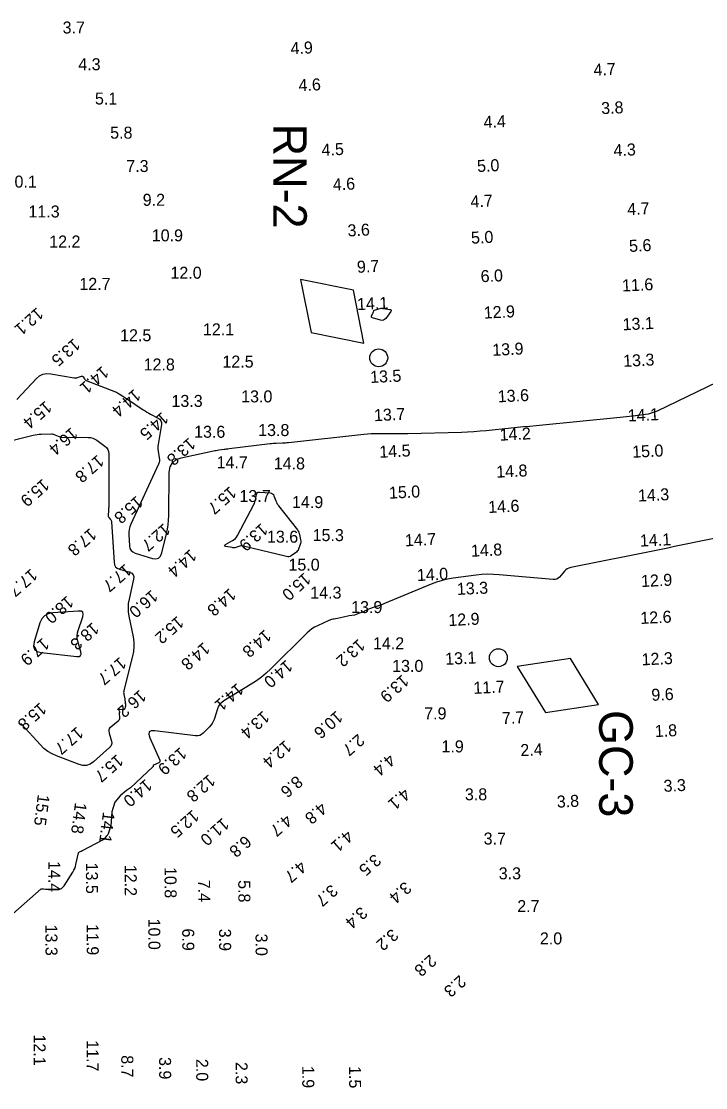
# Model space of a CAD drawing. Extents: x 824616 to 827440, y 158441 to 163197.
# Drawn here: x 824849.5 to 825134.8, y 161170.8 to 161615.4 of the extents above; entities that cross this region are included whole.
import ezdxf

# ---------------------------------------------------------------- set-up
doc = ezdxf.new("R2010")
doc.units = 0
for name, color, linetype in [('V-CHAN-CONT-EL14', 7, 'Continuous'), ('V-CHAN-CONT-EL16', 7, 'Continuous'), ('V-CHAN-CONT-EL18', 7, 'Continuous'), ('V-CHAN-NAID', 7, 'Continuous'), ('V-TOPO-SOUN', 7, 'Continuous')]:
    doc.layers.add(name, color=color, linetype=linetype)

msp = doc.modelspace()

# ---------------------------------------------------------------- linework, layer by layer
at = {"layer": 'V-CHAN-CONT-EL14'}
for points in [[(824996.49, 161494.89), (824996.58, 161494.95), (824996.69, 161495), (824999.41, 161495.78), (824999.49, 161495.8), (824999.58, 161495.8), (824999.66, 161495.8), (824999.74, 161495.78), (825000.08, 161495.67), (825000.17, 161495.65), (825000.25, 161495.63), (825000.34, 161495.61), (825000.43, 161495.6), (825003.11, 161495.3), (825003.49, 161495.2), (825003.68, 161495.02), (825003.68, 161494.76), (825003.49, 161494.42), (825001.37, 161491.53), (825000.93, 161491.07), (825000.43, 161490.8), (824999.87, 161490.71), (824999.24, 161490.8), (824995.8, 161491.79), (824995.58, 161491.89), (824995.46, 161492.03), (824995.43, 161492.21), (824995.49, 161492.44), (824996.04, 161493.72), (824996.09, 161493.84), (824996.14, 161493.95), (824996.18, 161494.07), (824996.22, 161494.2), (824996.37, 161494.69), (824996.42, 161494.8)], [(824946.81, 161414.9), (824946.96, 161415.42), (824947.07, 161415.96), (824947.45, 161418.13), (824947.6, 161418.6), (824947.86, 161418.92), (824948.24, 161419.1), (824948.74, 161419.13), (824953.24, 161418.78), (824953.77, 161418.68), (824954.2, 161418.45), (824954.54, 161418.09), (824954.78, 161417.61), (824955.57, 161415.44), (824955.79, 161414.91), (824956.04, 161414.4), (824956.34, 161413.92), (824956.67, 161413.45), (824964.57, 161403.34), (824964.88, 161402.9), (824965.13, 161402.43), (824965.33, 161401.93), (824965.47, 161401.41), (824965.92, 161399.2), (824965.99, 161398.7), (824965.99, 161398.2), (824965.91, 161397.71), (824965.76, 161397.23), (824965.03, 161395.31), (824964.81, 161394.85), (824964.53, 161394.44), (824964.19, 161394.09), (824963.79, 161393.78), (824961.95, 161392.57), (824961.49, 161392.33), (824961.01, 161392.2), (824960.51, 161392.17), (824960, 161392.24), (824942.13, 161396.62), (824941.72, 161396.69), (824941.32, 161396.71), (824940.92, 161396.67), (824940.52, 161396.57), (824938.92, 161396.06), (824938.52, 161395.96), (824938.12, 161395.91), (824937.71, 161395.92), (824937.3, 161395.97), (824934.77, 161396.45), (824934.35, 161396.57), (824934.18, 161396.75), (824934.28, 161396.96), (824934.64, 161397.23), (824937.57, 161398.92), (824938.18, 161399.33), (824938.72, 161399.82), (824939.18, 161400.38), (824939.57, 161401.01), (824946.37, 161413.9), (824946.61, 161414.39)]]:
    msp.add_lwpolyline(points, close=True, dxfattribs=at)
for points in [[(824847.55, 161457.69), (824855.79, 161466.49), (824857.08, 161467.58), (824858.49, 161468.28), (824860.04, 161468.57), (824861.72, 161468.47), (824871.48, 161466.8), (824871.84, 161466.76), (824872.21, 161466.77), (824872.57, 161466.81), (824872.92, 161466.91), (824874.6, 161467.44), (824874.81, 161467.48), (824875, 161467.45), (824875.17, 161467.34), (824875.3, 161467.17), (824875.79, 161466.32), (824875.93, 161466.13), (824876.09, 161465.96), (824876.27, 161465.83), (824876.49, 161465.72), (824888.72, 161460.89), (824889.13, 161460.72), (824889.54, 161460.52), (824889.93, 161460.3), (824890.31, 161460.07), (824891.82, 161459.08), (824892.19, 161458.83), (824892.57, 161458.59), (824892.94, 161458.34), (824893.32, 161458.09), (824900.31, 161453.44), (824901.06, 161452.96), (824901.83, 161452.49), (824902.6, 161452.05), (824903.39, 161451.62), (824906.57, 161449.96), (824907.24, 161449.49), (824907.68, 161448.9), (824907.89, 161448.19), (824907.86, 161447.37), (824906.45, 161438.94), (824906.37, 161438.25), (824906.35, 161437.57), (824906.38, 161436.88), (824906.48, 161436.2), (824907, 161433.46), (824907.07, 161432.78), (824907.05, 161432.12), (824906.91, 161431.46), (824906.67, 161430.82), (824895.09, 161405.73), (824894.67, 161404.67), (824894.4, 161403.59), (824894.26, 161402.47), (824894.26, 161401.33), (824894.55, 161396.73), (824894.75, 161395.67), (824895.21, 161394.83), (824895.93, 161394.18), (824896.9, 161393.74), (824904.14, 161391.51), (824905.57, 161391.29), (824906.7, 161391.59), (824907.53, 161392.41), (824908.06, 161393.75), (824909.95, 161401.75), (824910.35, 161403.63), (824910.63, 161405.51), (824910.82, 161407.42), (824910.9, 161409.33), (824911.17, 161427.4), (824911.5, 161429.64), (824912.44, 161431.39), (824913.97, 161432.65), (824916.11, 161433.41), (824929.62, 161436.3), (824930.16, 161436.41), (824930.7, 161436.51), (824931.24, 161436.6), (824931.79, 161436.69), (824933.98, 161437), (824934.52, 161437.08), (824935.07, 161437.16), (824935.62, 161437.23), (824936.16, 161437.29), (824953.16, 161439.36), (824953.8, 161439.43), (824954.44, 161439.48), (824955.08, 161439.53), (824955.72, 161439.56), (824958.3, 161439.66), (824958.94, 161439.69), (824959.58, 161439.73), (824960.22, 161439.78), (824960.86, 161439.84), (824992.2, 161443.24), (824993.73, 161443.39), (824995.25, 161443.49), (824996.78, 161443.54), (824998.31, 161443.55), (825004.43, 161443.51), (825005.96, 161443.5), (825007.49, 161443.51), (825009.03, 161443.53), (825010.56, 161443.57), (825032.91, 161444.18), (825035.51, 161444.28), (825038.11, 161444.42), (825040.71, 161444.61), (825043.3, 161444.85), (825053.66, 161445.89), (825056.26, 161446.15), (825058.85, 161446.41), (825061.44, 161446.67), (825064.03, 161446.92), (825099.04, 161450.39), (825100.37, 161450.53), (825101.69, 161450.67), (825103.01, 161450.81), (825104.34, 161450.97), (825109.63, 161451.59), (825110.93, 161451.8), (825112.21, 161452.11), (825113.46, 161452.53), (825114.67, 161453.06), (825139.69, 161465.12)], [(825161.56, 161404.52), (825124.51, 161397.04), (825123.82, 161396.9), (825123.13, 161396.75), (825122.44, 161396.6), (825121.75, 161396.44), (825118.99, 161395.81), (825118.3, 161395.65), (825117.61, 161395.5), (825116.92, 161395.35), (825116.23, 161395.21), (825078.51, 161387.69), (825077.76, 161387.48), (825077.08, 161387.16), (825076.46, 161386.72), (825075.91, 161386.17), (825073.84, 161383.73), (825073.29, 161383.21), (825072.67, 161382.85), (825071.98, 161382.67), (825071.22, 161382.66), (825048.68, 161384.69), (825046.28, 161384.84), (825043.89, 161384.86), (825041.49, 161384.74), (825039.1, 161384.49), (825029.55, 161383.22), (825027.18, 161382.82), (825024.85, 161382.28), (825022.56, 161381.58), (825020.32, 161380.73), (825000.86, 161372.65), (825000.36, 161372.45), (824999.86, 161372.25), (824999.35, 161372.06), (824998.84, 161371.88), (824996.54, 161371.09), (824996.16, 161370.96), (824995.79, 161370.83), (824995.41, 161370.69), (824995.04, 161370.55), (824993.54, 161369.99), (824993.21, 161369.82), (824992.67, 161369.58), (824992.2, 161369.28), (824991.4, 161368.91), (824990.38, 161368.61), (824988.32, 161367.82), (824986.08, 161367.52), (824983.78, 161366.97), (824981.29, 161366.43), (824980.5, 161366.29), (824979.9, 161366.15), (824979.42, 161366.13), (824978.78, 161365.95), (824977.65, 161365.6), (824972.88, 161363.37), (824971.72, 161362.76), (824970.62, 161362.07), (824969.59, 161361.28), (824968.62, 161360.4), (824953.45, 161345.41), (824951.55, 161343.64), (824949.56, 161341.99), (824947.48, 161340.46), (824945.3, 161339.04), (824933.85, 161332.07), (824932.99, 161331.43), (824932.27, 161330.68), (824931.7, 161329.82), (824931.29, 161328.83), (824929.82, 161324.32), (824929.49, 161323.46), (824929.06, 161322.66), (824928.54, 161321.92), (824927.93, 161321.23), (824925.28, 161318.6), (824924.59, 161318.03), (824923.83, 161317.67), (824923, 161317.49), (824922.11, 161317.51), (824905.18, 161319.66), (824903.67, 161319.65), (824902.8, 161319.17), (824902.59, 161318.2), (824903.01, 161316.75), (824907.18, 161307.4), (824907.28, 161307.04), (824907.24, 161306.73), (824907.07, 161306.48), (824906.75, 161306.28), (824904.55, 161305.29), (824904.49, 161305.26), (824904.46, 161305.22), (824904.43, 161305.17), (824904.43, 161305.1), (824904.44, 161304.84), (824904.43, 161304.77), (824904.41, 161304.71), (824904.38, 161304.66), (824904.34, 161304.61), (824894.92, 161295.9), (824893.28, 161294.72), (824890.66, 161292.5), (824888.39, 161289.81), (824887.15, 161285.77), (824886.77, 161279.88)], [(824830.5, 161229.86), (824857.8, 161253.75), (824858.65, 161253.69), (824859.51, 161253.64), (824860.37, 161253.6), (824861.22, 161253.59), (824864.66, 161253.58), (824865.46, 161253.67), (824866.17, 161253.94), (824866.78, 161254.39), (824867.29, 161255.02), (824870.93, 161260.75), (824871.37, 161261.5), (824871.73, 161262.28), (824872.03, 161263.09), (824872.25, 161263.92), (824873.33, 161268.68), (824873.39, 161268.84), (824873.47, 161268.97), (824873.59, 161269.08), (824873.73, 161269.16), (824874.37, 161269.43), (824874.53, 161269.5), (824874.68, 161269.57), (824874.84, 161269.65), (824874.99, 161269.73), (824883.49, 161274.17), (824883.75, 161274.32), (824883.98, 161274.49), (824884.2, 161274.69), (824884.4, 161274.91), (824885.17, 161275.82), (824885.35, 161276.06), (824885.51, 161276.31), (824885.65, 161276.57), (824885.76, 161276.84), (824886.68, 161279.32), (824886.79, 161279.71), (824886.77, 161279.88)]]:
    msp.add_lwpolyline(points, dxfattribs=at)
at = {"layer": 'V-CHAN-CONT-EL16'}
msp.add_lwpolyline([(824838.91, 161438.98), (824854.39, 161442.87), (824855.21, 161443.05), (824856.04, 161443.19), (824856.88, 161443.27), (824857.72, 161443.31), (824862.02, 161443.37), (824862.4, 161443.36), (824862.77, 161443.3), (824863.14, 161443.2), (824863.49, 161443.05), (824864.89, 161442.39), (824865.25, 161442.25), (824865.61, 161442.14), (824865.99, 161442.08), (824866.37, 161442.06), (824877.33, 161441.94), (824878.32, 161441.85), (824879.27, 161441.62), (824880.16, 161441.24), (824881.01, 161440.71), (824884.29, 161438.31), (824885.01, 161437.66), (824885.52, 161436.9), (824885.82, 161436.04), (824885.92, 161435.07), (824885.89, 161412.78), (824885.88, 161412.4), (824885.87, 161412.02), (824885.84, 161411.64), (824885.81, 161411.25), (824885.63, 161409.5), (824885.63, 161409.24), (824885.68, 161408.99), (824885.78, 161408.76), (824885.93, 161408.55), (824886.65, 161407.73), (824886.81, 161407.52), (824886.93, 161407.29), (824887.01, 161407.04), (824887.04, 161406.78), (824888.11, 161389.87), (824888.3, 161388.86), (824888.74, 161388.04), (824889.43, 161387.42), (824890.37, 161387), (824894.61, 161385.7), (824895.51, 161385.27), (824896.08, 161384.66), (824896.33, 161383.86), (824896.25, 161382.88), (824894.37, 161374.47), (824894.07, 161372.71), (824893.96, 161370.95), (824894.04, 161369.18), (824894.3, 161367.41), (824896.07, 161358.78), (824896.37, 161356.75), (824896.43, 161354.73), (824896.27, 161352.72), (824895.88, 161350.71), (824892.24, 161336.4), (824892.16, 161335.99), (824892.13, 161335.58), (824892.14, 161335.17), (824892.2, 161334.75), (824892.57, 161332.88), (824892.62, 161332.57), (824892.67, 161332.26), (824892.71, 161331.94), (824892.73, 161331.63), (824892.85, 161329.98), (824892.86, 161329.86), (824892.85, 161329.74), (824892.83, 161329.62), (824892.79, 161329.5), (824892.62, 161328.97), (824892.59, 161328.89), (824892.55, 161328.81), (824892.5, 161328.75), (824892.45, 161328.68), (824892.21, 161328.45), (824892.14, 161328.39), (824892.08, 161328.36), (824892, 161328.34), (824891.92, 161328.35), (824890.38, 161328.54), (824890.24, 161328.54), (824890.16, 161328.5), (824890.14, 161328.41), (824890.18, 161328.28), (824890.56, 161327.43), (824890.57, 161327.39), (824890.57, 161327.37), (824890.55, 161327.34), (824890.52, 161327.33), (824890.38, 161327.26), (824890.35, 161327.24), (824890.33, 161327.22), (824890.32, 161327.19), (824890.31, 161327.15), (824890.38, 161324.94), (824890.35, 161324.58), (824890.25, 161324.25), (824890.07, 161323.95), (824889.81, 161323.69), (824886.79, 161321.18), (824886.29, 161320.65), (824886, 161320.06), (824885.92, 161319.4), (824886.04, 161318.69), (824887.06, 161315.36), (824887.2, 161314.58), (824887.11, 161313.87), (824886.81, 161313.22), (824886.29, 161312.64), (824879.53, 161306.65), (824878.15, 161305.7), (824876.69, 161305.2), (824875.14, 161305.15), (824873.52, 161305.56), (824864.19, 161309.12), (824862.29, 161309.98), (824860.53, 161311.03), (824858.91, 161312.28), (824857.42, 161313.74), (824849.57, 161322.34), (824849.26, 161322.71)], dxfattribs=at)
at = {"layer": 'V-CHAN-CONT-EL18'}
msp.add_lwpolyline([(824854.97, 161353.59), (824856.02, 161352.7), (824857.74, 161352.25), (824872.57, 161350.58), (824873.54, 161350.61), (824874.15, 161350.95), (824874.39, 161351.6), (824874.25, 161352.56), (824872.99, 161357.05), (824872.76, 161358.17), (824872.71, 161359.28), (824872.83, 161360.39), (824873.12, 161361.49), (824875.07, 161367.11), (824875.29, 161368.24), (824875.06, 161369.02), (824874.37, 161369.45), (824873.22, 161369.53), (824862.56, 161368.79), (824860.68, 161368.42), (824859.17, 161367.59), (824858.02, 161366.31), (824857.24, 161364.56), (824854.84, 161356.67), (824854.57, 161354.91)], close=True, dxfattribs=at)
at = {"layer": 'V-CHAN-NAID'}
for points in [[(824992.29, 161481.27), (824987.88, 161503.31), (824965.84, 161507.72), (824970.25, 161485.68)], [(825056.24, 161346.39), (825067.92, 161327.19), (825090.14, 161330.59), (825078.46, 161349.79)]]:
    msp.add_lwpolyline(points, close=True, dxfattribs=at)
for centre in [(824998.46, 161475.1), (825048.33, 161350.08)]:
    msp.add_circle(centre, 3.74, dxfattribs=at)

# ---------------------------------------------------------------- texts
for s, p in [('RN-2', (824954.46, 161572.71)), ('GC-3', (825090.36, 161328.26))]:
    msp.add_text(s, height=14, rotation=270, dxfattribs=at).set_placement(p)
at = {"layer": 'V-TOPO-SOUN'}
for s, p in [('3.7', (824866.68, 161610.31)), ('4.3', (824873.23, 161594.99)), ('5.1', (824880.17, 161580.71)), ('5.8', (824886.51, 161566.47)), ('7.3', (824893.22, 161552.57)), ('10.1 ', (824842.91, 161546.06)), ('9.2', (824900.07, 161538.48)), ('11.3 ', (824852.44, 161533.61)), ('10.9 ', (824903.85, 161523.66)), ('12.2 ', (824861.11, 161521.09)), ('12.0 ', (824911.64, 161508.08)), ('12.7 ', (824873.67, 161503.44)), ('12.1 ', (824925.18, 161484.47)), ('12.5 ', (824890.65, 161482.01)), ('12.8 ', (824900.46, 161469.83)), ('12.5 ', (824933.3, 161471.03)), ('13.0 ', (824941.12, 161456.53)), ('13.3 ', (824912.06, 161454.63)), ('13.6 ', (824921.49, 161441.78)), ('13.8 ', (824948.2, 161442.49)), ('14.7 ', (824930.89, 161429.08)), ('14.8 ', (824954.71, 161428.57)), ('13.7 ', (824940.4, 161414.99)), ('14.9 ', (824962.31, 161412.47)), ('15.3 ', (824970.92, 161398.69)), ('13.6 ', (824951.87, 161398.04)), ('15.0 ', (824960.83, 161386.38)), ('14.3 ', (824969.91, 161374.72)), ('13.9 ', (824986.97, 161368.69)), ('14.2 ', (824996.06, 161353.58)), ('13.0 ', (825004.05, 161344.17)), ('7.9', (825017.42, 161324.38)), ('1.9', (825024.61, 161310.61)), ('3.8', (825034.38, 161290.64)), ('3.7', (825042.2, 161272.2)), ('3.3', (825048.48, 161257.7)), ('2.7', (825056.2, 161244.04)), ('2.0', (825065.64, 161230.58))]:
    msp.add_text(s, height=5, dxfattribs=at).set_placement(p)
for s, rotation, p in [('4.9', 2.7, (824961.82, 161601.61)), ('4.7', 2.7, (825088.09, 161592.68)), ('4.6', 2.7, (824965.15, 161586.23)), ('3.8', 2.7, (825091.31, 161576.67)), ('4.4', 2.7, (825042.27, 161570.88)), ('4.5', 2.7, (824974.73, 161559.28)), ('4.3', 2.7, (825096.45, 161559.11)), ('5.0', 2.7, (825039.57, 161552.55)), ('4.6', 2.7, (824979.44, 161544.85)), ('4.7', 2.7, (825036.81, 161537.76)), ('4.7', 2.7, (825102.17, 161534.56)), ('3.6', 2.7, (824985.57, 161525.68)), ('5.0', 2.7, (825037.06, 161522.65)), ('5.6', 2.7, (825102.94, 161519.23)), ('9.7', 2.7, (824989.49, 161510.51)), ('6.0', 2.7, (825041.05, 161506.61)), ('11.6 ', 2.7, (825100, 161502.72)), ('14.1 ', 2.7, (824989.52, 161494.97)), ('12.9 ', 2.7, (825042.36, 161491.43)), ('12.1 ', 221.3, (824855.98, 161496.39)), ('13.1 ', 2.7, (825100.24, 161486.55)), ('13.5 ', 221.3, (824871.32, 161483.49)), ('13.9 ', 2.7, (825045.91, 161475.91)), ('13.3 ', 2.7, (825100.46, 161471.32)), ('14.1 ', 221.3, (824883.21, 161471.98)), ('13.5 ', 2.7, (824994.99, 161464.6)), ('14.4 ', 221.3, (824896.55, 161462.4)), ('13.6 ', 2.7, (825048.19, 161456.52)), ('15.4 ', 221.3, (824859.52, 161457.46)), ('14.5 ', 221.6, (824908.12, 161452.82)), ('13.7 ', 2.7, (824996.6, 161448.66)), ('14.1 ', 2.7, (825102.38, 161448.54)), ('16.4 ', 221.3, (824870.32, 161446.43)), ('14.2 ', 2.7, (825048.98, 161440.54)), ('13.8 ', 221.6, (824919.39, 161442.12)), ('14.5 ', 2.7, (824998.81, 161433.42)), ('15.0 ', 2.7, (825104.23, 161433.43)), ('17.8 ', 221.3, (824881.23, 161434.94)), ('14.8 ', 2.7, (825047.56, 161425.11)), ('15.9 ', 221.3, (824858.43, 161424.97)), ('15.7 ', 221.6, (824936.41, 161421.82)), ('15.0 ', 2.7, (825002.83, 161416.35)), ('15.8 ', 221.3, (824897.49, 161417.87)), ('14.3 ', 2.7, (825106.65, 161415.17)), ('14.6 ', 2.7, (825044.19, 161410.4)), ('17.8 ', 221.3, (824878.14, 161404.39)), ('12.7 ', 221.3, (824908.87, 161406.38)), ('13.9 ', 221.6, (824949.54, 161406.43)), ('14.7 ', 2.7, (825009.48, 161396.51)), ('14.1 ', 2.7, (825107.44, 161396.38)), ('14.4 ', 221.3, (824919.85, 161395.56)), ('14.8 ', 2.7, (825037.02, 161392.16)), ('17.7 ', 221.3, (824853.48, 161387.47)), ('17.7 ', 221.3, (824892.74, 161389.46)), ('14.0 ', 2.7, (825014.5, 161382.03)), ('15.0 ', 221.6, (824967.44, 161385.82)), ('13.3 ', 2.7, (825031.15, 161376.23)), ('12.9 ', 2.7, (825107.92, 161379.53)), ('16.0 ', 221.3, (824903.71, 161378.64)), ('14.8 ', 221.3, (824936.27, 161379.31)), ('18.0 ', 221.3, (824868.57, 161376.2)), ('12.9 ', 2.7, (825027.6, 161363.26)), ('12.6 ', 2.7, (825107.63, 161364.14)), ('18.3 ', 221.3, (824879.16, 161365.1)), ('15.2 ', 221.3, (824914.52, 161367.75)), ('14.8 ', 221.3, (824950.96, 161362.06)), ('17.9 ', 221.3, (824858.44, 161358.67)), ('14.8 ', 221.3, (824925.4, 161356.79)), ('13.2 ', 221.6, (824990.02, 161358.18)), ('17.7 ', 221.3, (824890.57, 161350.66)), ('13.1 ', 2.7, (825026.26, 161347.1)), ('12.3 ', 2.7, (825108.15, 161346.87)), ('14.0 ', 221.3, (824959.88, 161349.44)), ('13.9 ', 221.6, (825008.29, 161343.35)), ('16.2 ', 221.3, (824898.85, 161336.99)), ('14.1 ', 221.3, (824939.41, 161339.78)), ('11.7 ', 2.7, (825038.02, 161334.99)), ('9.6', 2.7, (825112.23, 161332.08)), ('15.8 ', 221.3, (824857.27, 161331.68)), ('13.4 ', 221.3, (824950.22, 161328.23)), ('10.6 ', 221.3, (824980.77, 161328.25)), ('7.7', 2.7, (825049.93, 161322.36)), ('17.7 ', 221.3, (824872.67, 161321.65)), ('1.8', 2.7, (825113.66, 161316.99)), ('12.4 ', 221.3, (824959.43, 161316)), ('2.7', 221.3, (824989.83, 161318.61)), ('2.4', 2.7, (825057.62, 161309.03)), ('13.9 ', 221.3, (824915.72, 161313.06)), ('15.7 ', 221.3, (824889.33, 161310.12)), ('4.4', 221.3, (825002.66, 161310.3)), ('12.8 ', 221.3, (824927.66, 161301.75)), ('14.0 ', 221.3, (824901.31, 161299.81)), ('8.6', 221.3, (824964.07, 161301.23)), ('3.3', 2.7, (825117.32, 161294.14)), ('15.5 ', 262.6, (824856.38, 161293.28)), ('4.1', 221.3, (825008.9, 161296.05)), ('3.8', 2.7, (825072.81, 161287.56)), ('14.8 ', 262.6, (824871.88, 161289.92)), ('4.8', 221.3, (824974.2, 161290.13)), ('14.1 ', 262.6, (824883.55, 161285.98)), ('12.5 ', 221.3, (824920.87, 161286.98)), ('11.0 ', 221.3, (824933.4, 161283.61)), ('4.7', 221.3, (824959.67, 161285.06)), ('6.8', 221.3, (824942.68, 161276.29)), ('4.1', 221.3, (824985.1, 161278.51)), ('3.5', 221.3, (824996.72, 161268.59)), ('14.4 ', 270.3, (824860.73, 161265.33)), ('13.5 ', 270.3, (824876.38, 161264.66)), ('12.2 ', 270.3, (824892.56, 161263.73)), ('10.8 ', 270.3, (824909.16, 161262.83)), ('4.7', 221.3, (824965.67, 161265.78)), ('7.4', 270.3, (824923.18, 161257.52)), ('5.8', 270.3, (824939.9, 161257.36)), ('3.7', 221.3, (824978.67, 161255.87)), ('3.4', 221.3, (825009.38, 161257.06)), ('3.4', 221.3, (824991.03, 161246.6)), ('10.0 ', 270.3, (824902.38, 161241.32)), ('13.3 ', 270.3, (824859.49, 161238.83)), ('11.9 ', 270.3, (824876.69, 161239.05)), ('6.9', 270.3, (824916.54, 161237.2)), ('3.9', 270.3, (824931.89, 161237.1)), ('3.0', 270.3, (824947.1, 161235.06)), ('3.2', 221.3, (825003.94, 161237.39)), ('2.8', 221.3, (825019.83, 161226.63)), ('2.3', 221.3, (825032.15, 161218.02)), ('12.1 ', 270.3, (824854.58, 161193.03)), ('11.7 ', 270.3, (824876.67, 161190.63)), ('8.7', 270.3, (824891.14, 161184.37)), ('3.9', 270.3, (824906.89, 161183.59)), ('2.0', 270.3, (824922.36, 161182.83)), ('2.3', 270.3, (824938.78, 161181.54)), ('1.9', 270.3, (824966.55, 161179.94)), ('1.5', 270.3, (824986.09, 161179.85))]:
    msp.add_text(s, height=5, rotation=rotation, dxfattribs=at).set_placement(p)

doc.saveas('drawing.dxf')
